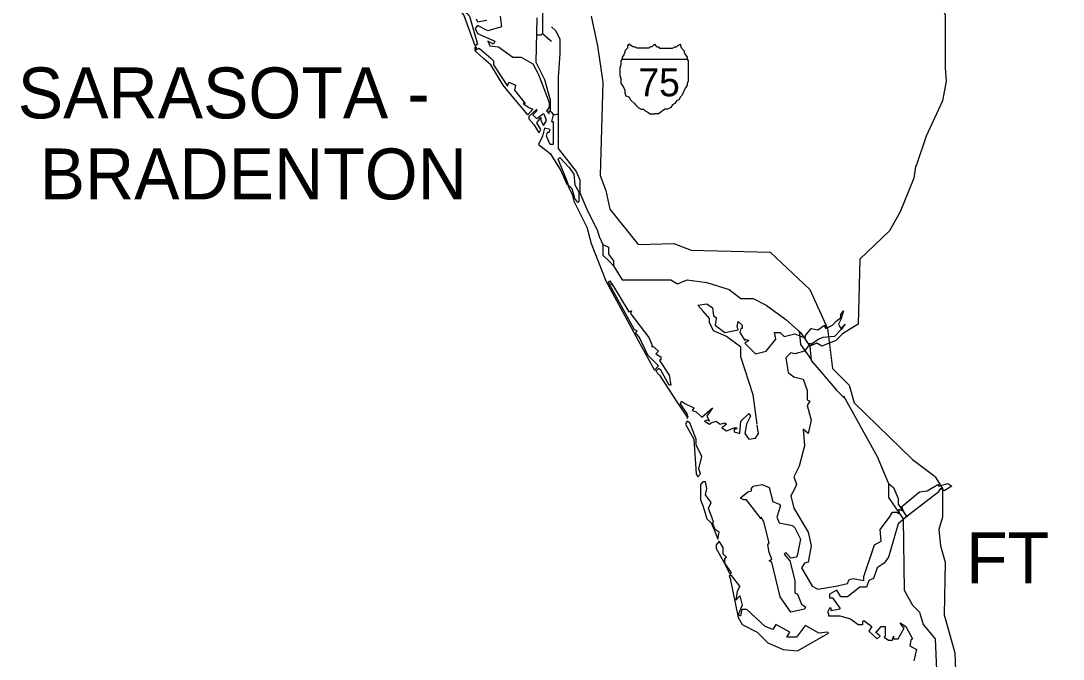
# Model space of a CAD drawing. Extents: x -820.2 to -798.1, y -2199.1 to -2182.2.
# Drawn here: x -806.711 to -805.79, y -2185.475 to -2184.911 of the extents above; entities that cross this region are included whole.
import ezdxf

# ---------------------------------------------------------------- set-up
doc = ezdxf.new("R2010")
doc.units = 0
for name, color, linetype in [('FLMap1', 7, 'Continuous'), ('FLMap2', 7, 'Continuous'), ('FLMap3', 7, 'Continuous'), ('TextMisc', 7, 'Continuous')]:
    doc.layers.add(name, color=color, linetype=linetype)

msp = doc.modelspace()

# ---------------------------------------------------------------- linework, layer by layer
at = {"layer": 'FLMap1'}
msp.add_line((-806.1797, -2184.94505), (-806.12215, -2184.94505), dxfattribs=at)
for points in [[(-806.15092, -2184.93165), (-806.15241, -2184.93314), (-806.1534, -2184.93413), (-806.15489, -2184.93413), (-806.15588, -2184.93513), (-806.15688, -2184.93513), (-806.15936, -2184.93513), (-806.16084, -2184.93513), (-806.16184, -2184.93513), (-806.16283, -2184.93513), (-806.16432, -2184.93513), (-806.16531, -2184.93513), (-806.1663, -2184.93513), (-806.16878, -2184.93413), (-806.17027, -2184.93413), (-806.17126, -2184.93314), (-806.17374, -2184.93165), (-806.17474, -2184.93314), (-806.17474, -2184.93513), (-806.17622, -2184.93661), (-806.17722, -2184.93761), (-806.17722, -2184.9391), (-806.17821, -2184.94108), (-806.1797, -2184.94306), (-806.1797, -2184.94505), (-806.18069, -2184.94654), (-806.18069, -2184.95001), (-806.18168, -2184.95249), (-806.18168, -2184.95497), (-806.18168, -2184.95696), (-806.18168, -2184.95944), (-806.18069, -2184.96192), (-806.18069, -2184.9644), (-806.18069, -2184.96638), (-806.1797, -2184.96787), (-806.17821, -2184.97035), (-806.17722, -2184.97234), (-806.17722, -2184.97482), (-806.17622, -2184.9773), (-806.17374, -2184.97829), (-806.17226, -2184.98077), (-806.17126, -2184.98176), (-806.16878, -2184.98424), (-806.16779, -2184.98523), (-806.16531, -2184.98772), (-806.16283, -2184.9892), (-806.16084, -2184.9892), (-806.15936, -2184.99069), (-806.15688, -2184.99168), (-806.15489, -2184.99317), (-806.15092, -2184.99317)], [(-806.15092, -2184.93165), (-806.14993, -2184.93314), (-806.14894, -2184.93413), (-806.14745, -2184.93413), (-806.14646, -2184.93513), (-806.14546, -2184.93513), (-806.14398, -2184.93513), (-806.1415, -2184.93513), (-806.1405, -2184.93513), (-806.13951, -2184.93513), (-806.13802, -2184.93513), (-806.13653, -2184.93513), (-806.13505, -2184.93513), (-806.13306, -2184.93413), (-806.13157, -2184.93413), (-806.13058, -2184.93314), (-806.1281, -2184.93165), (-806.1281, -2184.93314), (-806.12711, -2184.93513), (-806.12562, -2184.93661), (-806.12463, -2184.93761), (-806.12463, -2184.9391), (-806.12364, -2184.94108), (-806.12215, -2184.94306), (-806.12215, -2184.94505), (-806.12115, -2184.94654), (-806.12115, -2184.95001), (-806.12115, -2184.95249), (-806.12115, -2184.95497), (-806.12115, -2184.95696), (-806.12115, -2184.95944), (-806.12115, -2184.96192), (-806.12115, -2184.9644), (-806.12215, -2184.96638), (-806.12215, -2184.96787), (-806.12364, -2184.97035), (-806.12463, -2184.97234), (-806.12562, -2184.97482), (-806.12711, -2184.9773), (-806.1281, -2184.97829), (-806.12959, -2184.98077), (-806.13157, -2184.98176), (-806.13306, -2184.98424), (-806.13505, -2184.98523), (-806.13653, -2184.98772), (-806.13951, -2184.9892), (-806.1415, -2184.9892), (-806.14398, -2184.99069), (-806.14546, -2184.99168), (-806.14745, -2184.99317), (-806.15092, -2184.99317)]]:
    msp.add_lwpolyline(points, dxfattribs=at)
at = {"layer": 'FLMap2'}
for points in [[(-805.89641, -2184.78381), (-805.90137, -2184.80564), (-805.90385, -2184.80762), (-805.90633, -2184.8101), (-805.90633, -2184.82548), (-805.90733, -2184.84334), (-805.90038, -2184.88303), (-805.89939, -2184.89395), (-805.89393, -2184.90585), (-805.89393, -2184.95249), (-805.89294, -2184.9644), (-805.89641, -2184.98176), (-805.9108, -2185.01302), (-805.91923, -2185.03832)], [(-806.23725, -2184.83243), (-806.23824, -2184.85773), (-806.24072, -2184.86865), (-806.24419, -2184.87113), (-806.25015, -2184.88055), (-806.24816, -2184.8875), (-806.25015, -2184.89643), (-806.25015, -2184.92223), (-806.25164, -2184.92372), (-806.25511, -2184.92372)], [(-806.33399, -2184.8875), (-806.33498, -2184.88502), (-806.33399, -2184.88403), (-806.31712, -2184.89246), (-806.3196, -2184.90238), (-806.31812, -2184.90337), (-806.31712, -2184.90437), (-806.31464, -2184.90685), (-806.3077, -2184.93165), (-806.30968, -2184.93314), (-806.3196, -2184.90585), (-806.33399, -2184.8875)], [(-806.28736, -2184.90685), (-806.28636, -2184.91627), (-806.29827, -2184.91975), (-806.3077, -2184.91528), (-806.30968, -2184.91776), (-806.3077, -2184.92223), (-806.29232, -2184.92917), (-806.29331, -2184.93165), (-806.29827, -2184.92917), (-806.29678, -2184.93314), (-806.28884, -2184.93413), (-806.27644, -2184.94306), (-806.269, -2184.94306)], [(-806.30869, -2184.90933), (-806.3077, -2184.91181), (-806.29926, -2184.91032)], [(-806.25511, -2184.90834), (-806.2561, -2184.94753), (-806.24816, -2184.96291), (-806.2432, -2184.98077), (-806.2432, -2184.99069), (-806.23973, -2184.99416), (-806.23626, -2184.99317), (-806.23626, -2184.99416), (-806.23626, -2185.02393), (-806.22038, -2185.04427), (-806.21691, -2185.05172), (-806.21691, -2185.06313), (-806.21095, -2185.07751), (-806.20153, -2185.09686), (-806.20004, -2185.10182), (-806.19657, -2185.10877), (-806.1916, -2185.11125), (-806.1916, -2185.11224), (-806.1916, -2185.1172), (-806.18714, -2185.12316), (-806.18714, -2185.12762), (-806.1797, -2185.14003), (-806.13653, -2185.14003), (-806.13058, -2185.1435), (-806.12215, -2185.14003), (-806.10478, -2185.14251), (-806.08494, -2185.14846)], [(-806.25015, -2184.92223), (-806.2432, -2184.92818), (-806.24221, -2184.92917)], [(-806.24221, -2184.91627), (-806.23824, -2184.91975), (-806.23477, -2184.92719), (-806.23477, -2184.94009), (-806.23626, -2184.96043), (-806.23626, -2184.99317)], [(-806.30968, -2184.93413), (-806.30869, -2184.93413), (-806.30869, -2184.93661), (-806.30621, -2184.93513), (-806.29579, -2184.94406), (-806.29331, -2184.94654), (-806.29331, -2184.95001), (-806.28091, -2184.96886), (-806.27991, -2184.96539), (-806.27396, -2184.96787), (-806.27495, -2184.97234), (-806.26553, -2184.98424), (-806.26702, -2184.98424), (-806.26205, -2184.98772), (-806.25858, -2184.9892), (-806.26305, -2184.99416), (-806.27843, -2184.97581), (-806.28488, -2184.96787), (-806.29579, -2184.95001), (-806.30174, -2184.94505), (-806.30968, -2184.93761), (-806.30968, -2184.93661), (-806.30968, -2184.93413)], [(-806.269, -2184.94306), (-806.25858, -2184.94902), (-806.25362, -2184.95844), (-806.24419, -2184.98325), (-806.24419, -2184.98772), (-806.24667, -2184.99069), (-806.24419, -2184.99317), (-806.24419, -2184.99069), (-806.24221, -2184.99168), (-806.24072, -2184.99416), (-806.24221, -2185.00012), (-806.24221, -2185.00012), (-806.24072, -2185.00012), (-806.24072, -2185.02046), (-806.2432, -2185.02046), (-806.24667, -2185.01302), (-806.24568, -2185.00954), (-806.24419, -2185.00954), (-806.2432, -2185.00706), (-806.24816, -2185.00607), (-806.25015, -2185.01302), (-806.25362, -2185.02046), (-806.2432, -2185.0284), (-806.23378, -2185.04328), (-806.22832, -2185.05618), (-806.22733, -2185.05519), (-806.23626, -2185.03336), (-806.23477, -2185.03187), (-806.22633, -2185.0408), (-806.22236, -2185.04675), (-806.22137, -2185.05618)], [(-806.25511, -2184.9892), (-806.26205, -2184.99565), (-806.26205, -2184.99665), (-806.26205, -2184.99764), (-806.25759, -2185.0026), (-806.25362, -2185.00954), (-806.25263, -2185.00954), (-806.25164, -2185.00706), (-806.25511, -2185.00111), (-806.25164, -2184.99665), (-806.25164, -2184.99913), (-806.24915, -2185.00359), (-806.24667, -2184.99913), (-806.24816, -2184.99416), (-806.24915, -2184.99317), (-806.25511, -2184.99764), (-806.25858, -2184.99416), (-806.25511, -2184.99069), (-806.25511, -2184.9892)], [(-805.91923, -2185.03832), (-805.92022, -2185.03981), (-805.92171, -2185.05023), (-805.93362, -2185.07999), (-805.94305, -2185.09686), (-805.96934, -2185.12167), (-805.97083, -2185.17922), (-805.98472, -2185.18765), (-805.99067, -2185.19361), (-806.00308, -2185.19857), (-806.00754, -2185.19609), (-806.00754, -2185.19609), (-806.0135, -2185.19857)], [(-806.22137, -2185.05618), (-806.2179, -2185.06213), (-806.2179, -2185.07057), (-806.21889, -2185.07156), (-806.22137, -2185.06809), (-806.22385, -2185.05965), (-806.22385, -2185.05965), (-806.22733, -2185.05618), (-806.22733, -2185.05717), (-806.22385, -2185.06461), (-806.22236, -2185.07057), (-806.21095, -2185.09339), (-806.20698, -2185.10778), (-806.19409, -2185.14102), (-806.17722, -2185.17178), (-806.16531, -2185.19361)], [(-806.19657, -2185.10877), (-806.19657, -2185.11125), (-806.19657, -2185.1182), (-806.19061, -2185.12415), (-806.18714, -2185.12762)], [(-806.16779, -2185.18666), (-806.1663, -2185.18517), (-806.16878, -2185.18418), (-806.1916, -2185.14251), (-806.19061, -2185.14102), (-806.18962, -2185.14251), (-806.18813, -2185.1435), (-806.18962, -2185.1435), (-806.18813, -2185.14449), (-806.17374, -2185.1683), (-806.17126, -2185.16731), (-806.17226, -2185.16979), (-806.15588, -2185.19113), (-806.1534, -2185.19708), (-806.1534, -2185.19956), (-806.15241, -2185.19857), (-806.14745, -2185.20303), (-806.14993, -2185.20551), (-806.14546, -2185.20799), (-806.14546, -2185.21048), (-806.14646, -2185.21147), (-806.13802, -2185.22437), (-806.13653, -2185.2333), (-806.13802, -2185.2333), (-806.14546, -2185.2199)], [(-806.08494, -2185.14846), (-806.07452, -2185.1564), (-806.0636, -2185.1564), (-806.05219, -2185.16235), (-806.03483, -2185.17525), (-806.02193, -2185.18666), (-806.0135, -2185.19857), (-806.0125, -2185.21147), (-805.98968, -2185.23776), (-805.98224, -2185.2452)], [(-806.06013, -2185.26753), (-806.0636, -2185.24173), (-806.07452, -2185.20799), (-806.07452, -2185.19956), (-806.08742, -2185.19013), (-806.09883, -2185.18517), (-806.1023, -2185.17773), (-806.1023, -2185.17426), (-806.10826, -2185.16731), (-806.11272, -2185.16235), (-806.10478, -2185.16136), (-806.09982, -2185.16483), (-806.09883, -2185.17178), (-806.09635, -2185.17327), (-806.09635, -2185.17426), (-806.09734, -2185.18021), (-806.08891, -2185.18666), (-806.077, -2185.18418), (-806.07799, -2185.1812), (-806.077, -2185.17674), (-806.07353, -2185.18021), (-806.07353, -2185.18319), (-806.07452, -2185.18319), (-806.07551, -2185.18666), (-806.07105, -2185.19361), (-806.07105, -2185.19261), (-806.06757, -2185.19361), (-806.07105, -2185.19609), (-806.06162, -2185.20551), (-806.05219, -2185.20303), (-806.04376, -2185.19261), (-806.04475, -2185.18666), (-806.03979, -2185.18666), (-806.03632, -2185.19013), (-806.02689, -2185.18765), (-806.02094, -2185.19013), (-806.01846, -2185.19113), (-806.01746, -2185.19113), (-806.01746, -2185.18914), (-806.0125, -2185.18319), (-806.00655, -2185.18418), (-806.0006, -2185.18021), (-805.9996, -2185.1812), (-806.0006, -2185.1812), (-805.9996, -2185.18319), (-805.99365, -2185.18021), (-805.99067, -2185.17674), (-805.98621, -2185.17327), (-805.98621, -2185.17079), (-805.98373, -2185.16731), (-805.98621, -2185.17525), (-805.98819, -2185.17922), (-805.98621, -2185.18319), (-805.98224, -2185.17922), (-805.98621, -2185.18418), (-805.99167, -2185.19013), (-806.00208, -2185.19113), (-806.00556, -2185.19261), (-806.0125, -2185.19708), (-806.0135, -2185.19609), (-806.01498, -2185.19857), (-806.01846, -2185.20303), (-806.02689, -2185.20551), (-806.03036, -2185.20452), (-806.03483, -2185.20899), (-806.03284, -2185.22189), (-806.02788, -2185.22586), (-806.01945, -2185.22784), (-806.01598, -2185.23776), (-806.01598, -2185.2462), (-806.0135, -2185.24719), (-806.01598, -2185.25116), (-806.0125, -2185.26406)], [(-806.16531, -2185.19361), (-806.15092, -2185.2199), (-806.14745, -2185.21593), (-806.15688, -2185.20651), (-806.16432, -2185.19113), (-806.16779, -2185.18666)], [(-806.02292, -2185.18517), (-806.02193, -2185.19708), (-806.01598, -2185.20551), (-806.0125, -2185.21048)], [(-806.14546, -2185.2199), (-806.14745, -2185.21841), (-806.14993, -2185.22089), (-806.14646, -2185.22437), (-806.13058, -2185.24868)], [(-805.98373, -2185.24272), (-805.95396, -2185.2963), (-805.94404, -2185.32012), (-805.93957, -2185.32359), (-805.9356, -2185.33351), (-805.9356, -2185.33848), (-805.92767, -2185.34989)], [(-806.13058, -2185.24868), (-806.12215, -2185.26158), (-806.12215, -2185.26257), (-806.12115, -2185.26158), (-806.12215, -2185.2591), (-806.12215, -2185.2581), (-806.12562, -2185.25314), (-806.1281, -2185.24967), (-806.12711, -2185.24719), (-806.12364, -2185.24967), (-806.11619, -2185.25314), (-806.11768, -2185.25562), (-806.11421, -2185.25661), (-806.10925, -2185.26158), (-806.09982, -2185.25314), (-806.10478, -2185.26058), (-806.1023, -2185.26505), (-806.10478, -2185.26406), (-806.10677, -2185.26505), (-806.1023, -2185.26753), (-806.10081, -2185.26654), (-806.09635, -2185.26505), (-806.09288, -2185.26753), (-806.08891, -2185.26654), (-806.08742, -2185.26753), (-806.09139, -2185.271), (-806.08742, -2185.27348), (-806.08047, -2185.271), (-806.07799, -2185.271), (-806.07898, -2185.27199), (-806.08047, -2185.27199), (-806.08047, -2185.27448), (-806.07551, -2185.27596), (-806.07452, -2185.26505), (-806.06757, -2185.2581), (-806.06609, -2185.26058), (-806.06956, -2185.26753), (-806.07105, -2185.27596), (-806.06757, -2185.28092), (-806.06162, -2185.27993), (-806.05914, -2185.27596), (-806.06013, -2185.26852)], [(-806.0125, -2185.26406), (-806.01498, -2185.27596), (-806.01945, -2185.27199), (-806.01846, -2185.28688), (-806.02292, -2185.30474), (-806.02788, -2185.31417), (-806.0254, -2185.32111), (-806.02689, -2185.32458), (-806.03036, -2185.33103), (-806.02788, -2185.34195), (-806.01498, -2185.36328), (-806.0125, -2185.37519), (-806.01498, -2185.38958), (-806.01846, -2185.39057), (-806.02094, -2185.39454), (-806.01151, -2185.41091), (-806.00655, -2185.41339), (-805.99067, -2185.41091), (-805.98026, -2185.40843), (-805.97877, -2185.40496), (-805.97529, -2185.40396), (-805.96587, -2185.40595), (-805.96587, -2185.40248), (-805.95644, -2185.3742), (-805.95049, -2185.37122), (-805.95148, -2185.3608), (-805.94305, -2185.34989), (-805.94057, -2185.34542), (-805.93709, -2185.34542), (-805.9356, -2185.34641), (-805.93461, -2185.34641), (-805.93461, -2185.34393), (-805.93461, -2185.34294), (-805.93213, -2185.34393), (-805.93114, -2185.34393), (-805.93213, -2185.34046), (-805.91675, -2185.32756), (-805.90981, -2185.32657), (-805.90038, -2185.32111), (-805.89939, -2185.3226), (-805.89145, -2185.32012), (-805.88798, -2185.3226), (-805.89492, -2185.32657), (-805.8979, -2185.32458), (-805.89939, -2185.32657), (-805.89939, -2185.32756), (-805.92767, -2185.34889), (-805.92767, -2185.34889), (-805.9356, -2185.35584), (-805.94404, -2185.38511), (-805.94801, -2185.39057), (-805.95396, -2185.39454), (-805.95743, -2185.40396), (-805.9614, -2185.40595), (-805.96339, -2185.4119), (-805.96934, -2185.4119), (-805.98026, -2185.42034), (-805.98621, -2185.42034), (-805.98968, -2185.41438), (-805.99613, -2185.41786), (-805.99613, -2185.42133), (-805.99365, -2185.42133), (-805.9872, -2185.43026)], [(-806.11967, -2185.26654), (-806.12215, -2185.26505), (-806.12364, -2185.26753)], [(-806.12364, -2185.26753), (-806.11619, -2185.28092), (-806.11421, -2185.31168), (-806.11272, -2185.31417), (-806.11024, -2185.31168), (-806.11173, -2185.30722), (-806.10925, -2185.2963), (-806.11421, -2185.28589), (-806.11421, -2185.28092), (-806.11967, -2185.26654)], [(-806.10478, -2185.32458), (-806.10577, -2185.31863), (-806.10826, -2185.31863), (-806.11024, -2185.32111)], [(-805.94404, -2185.32012), (-805.94404, -2185.33252), (-805.93114, -2185.35137), (-805.93015, -2185.41438), (-805.92271, -2185.42778), (-805.91675, -2185.43373), (-805.91328, -2185.44465), (-805.90286, -2185.45755), (-805.89939, -2185.53296)], [(-806.11024, -2185.32111), (-806.11024, -2185.33451), (-806.10826, -2185.33947), (-806.10478, -2185.35137), (-806.10081, -2185.35485), (-806.09734, -2185.36328), (-806.09486, -2185.36923), (-806.09387, -2185.36328), (-806.09734, -2185.3608), (-806.09982, -2185.35485), (-806.09883, -2185.35386), (-806.10329, -2185.34195), (-806.10081, -2185.33699), (-806.10577, -2185.33004), (-806.10478, -2185.32458)], [(-806.07452, -2185.33252), (-806.06857, -2185.32756), (-806.06509, -2185.32657), (-806.06509, -2185.32458), (-806.0636, -2185.3226), (-806.05567, -2185.32111), (-806.04971, -2185.32359), (-806.04624, -2185.33599), (-806.04078, -2185.33848), (-806.03979, -2185.33947), (-806.03979, -2185.34046), (-806.04277, -2185.34989), (-806.04078, -2185.35485), (-806.02888, -2185.35733), (-806.02689, -2185.35931), (-806.02193, -2185.36923), (-806.02441, -2185.38263), (-806.0254, -2185.38511), (-806.03036, -2185.3861), (-806.03483, -2185.38114), (-806.03632, -2185.38263), (-806.03136, -2185.38858), (-806.02689, -2185.40595), (-806.02689, -2185.41686), (-806.02441, -2185.41786), (-806.02094, -2185.42679), (-806.01746, -2185.42927), (-806.01846, -2185.43125), (-806.03036, -2185.43373), (-806.03979, -2185.42034), (-806.04723, -2185.38958), (-806.04971, -2185.38858), (-806.04723, -2185.3871), (-806.04971, -2185.38114), (-806.05071, -2185.3742), (-806.05071, -2185.3742), (-806.04971, -2185.37271), (-806.05418, -2185.35386), (-806.05666, -2185.34989), (-806.05666, -2185.35137), (-806.06956, -2185.33451)], [(-806.06956, -2185.33451), (-806.07204, -2185.33451), (-806.07452, -2185.33351), (-806.07452, -2185.33252)], [(-806.0904, -2185.37668), (-806.09387, -2185.37122), (-806.09635, -2185.3742), (-806.09635, -2185.37767), (-806.0904, -2185.38858), (-806.08494, -2185.399), (-806.08395, -2185.39999), (-806.08295, -2185.399), (-806.08891, -2185.39057), (-806.08891, -2185.3861), (-806.08742, -2185.38511), (-806.0904, -2185.38263), (-806.0904, -2185.37668), (-806.09387, -2185.37122)], [(-806.07551, -2185.41091), (-806.08295, -2185.40148), (-806.08494, -2185.40148), (-806.08395, -2185.40396), (-806.077, -2185.43869), (-806.07353, -2185.44465), (-806.06013, -2185.45159), (-806.05071, -2185.46102), (-806.03731, -2185.46697), (-806.02441, -2185.46796), (-805.99712, -2185.45258), (-805.99812, -2185.45159), (-806.00556, -2185.45258), (-806.01746, -2185.44564), (-806.01846, -2185.44663), (-806.0254, -2185.45606), (-806.03384, -2185.45606), (-806.03136, -2185.45159), (-806.04376, -2185.44465), (-806.04624, -2185.44911), (-806.05319, -2185.44663), (-806.06956, -2185.43125)], [(-806.07551, -2185.41091), (-806.07799, -2185.41537), (-806.07898, -2185.42331), (-806.07551, -2185.41934), (-806.07353, -2185.42778), (-806.077, -2185.43621), (-806.07452, -2185.4372), (-806.07353, -2185.43125), (-806.06956, -2185.43125)], [(-805.9872, -2185.43026), (-805.9872, -2185.43125), (-805.99464, -2185.43274), (-805.99464, -2185.43026), (-805.99613, -2185.43026), (-805.99812, -2185.43373), (-805.99712, -2185.43522), (-805.99712, -2185.4372), (-805.9872, -2185.4372), (-805.97777, -2185.43968), (-805.97083, -2185.44465), (-805.96686, -2185.44465), (-805.96686, -2185.44316), (-805.96686, -2185.44217), (-805.96587, -2185.44117), (-805.95892, -2185.44663), (-805.9614, -2185.4506), (-805.95396, -2185.45755), (-805.95148, -2185.45506), (-805.95545, -2185.45159), (-805.95396, -2185.4506), (-805.95049, -2185.44663), (-805.94702, -2185.44663), (-805.94702, -2185.45506), (-805.94801, -2185.45606), (-805.94404, -2185.45854), (-805.94057, -2185.45854), (-805.93957, -2185.45506), (-805.93957, -2185.45606), (-805.93957, -2185.45755), (-805.93808, -2185.45755), (-805.9356, -2185.45755), (-805.93015, -2185.44812), (-805.93213, -2185.44564), (-805.93362, -2185.44316), (-805.92866, -2185.44663), (-805.92271, -2185.45755), (-805.92419, -2185.45854), (-805.92519, -2185.4635), (-805.91923, -2185.46697), (-805.92171, -2185.47689)]]:
    msp.add_lwpolyline(points, dxfattribs=at)
at = {"layer": 'FLMap3'}
msp.add_lwpolyline([(-806.20698, -2184.90685), (-806.20153, -2184.93314), (-806.19657, -2184.96539), (-806.19905, -2185.04775), (-806.19409, -2185.06114), (-806.19061, -2185.07751), (-806.16531, -2185.10877), (-806.13405, -2185.10778), (-806.11867, -2185.11373), (-806.04872, -2185.11572), (-806.0135, -2185.14846), (-805.99812, -2185.18319), (-805.99365, -2185.21841), (-805.97877, -2185.2333), (-805.9743, -2185.24868), (-805.92271, -2185.29879), (-805.90385, -2185.31317), (-805.90286, -2185.31417), (-805.89641, -2185.32458), (-805.89641, -2185.34989), (-805.89939, -2185.3608), (-805.8979, -2185.37519), (-805.89393, -2185.38958), (-805.89492, -2185.43621), (-805.8855, -2185.46995), (-805.8845, -2185.49327)], dxfattribs=at)

# ---------------------------------------------------------------- texts
at = {"layer": 'TextMisc'}
for s, height, p in [('SARASOTA -', 0.045, (-806.71418, -2184.99727)), ('75', 0.024695, (-806.16533, -2184.97779)), ('BRADENTON', 0.045, (-806.69482, -2185.06891)), ('FT MYERS', 0.045, (-805.87549, -2185.40843))]:
    msp.add_text(s, height=height, dxfattribs=at).set_placement(p)

doc.saveas('drawing.dxf')
